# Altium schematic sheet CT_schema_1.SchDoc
size 486 x 446 mm
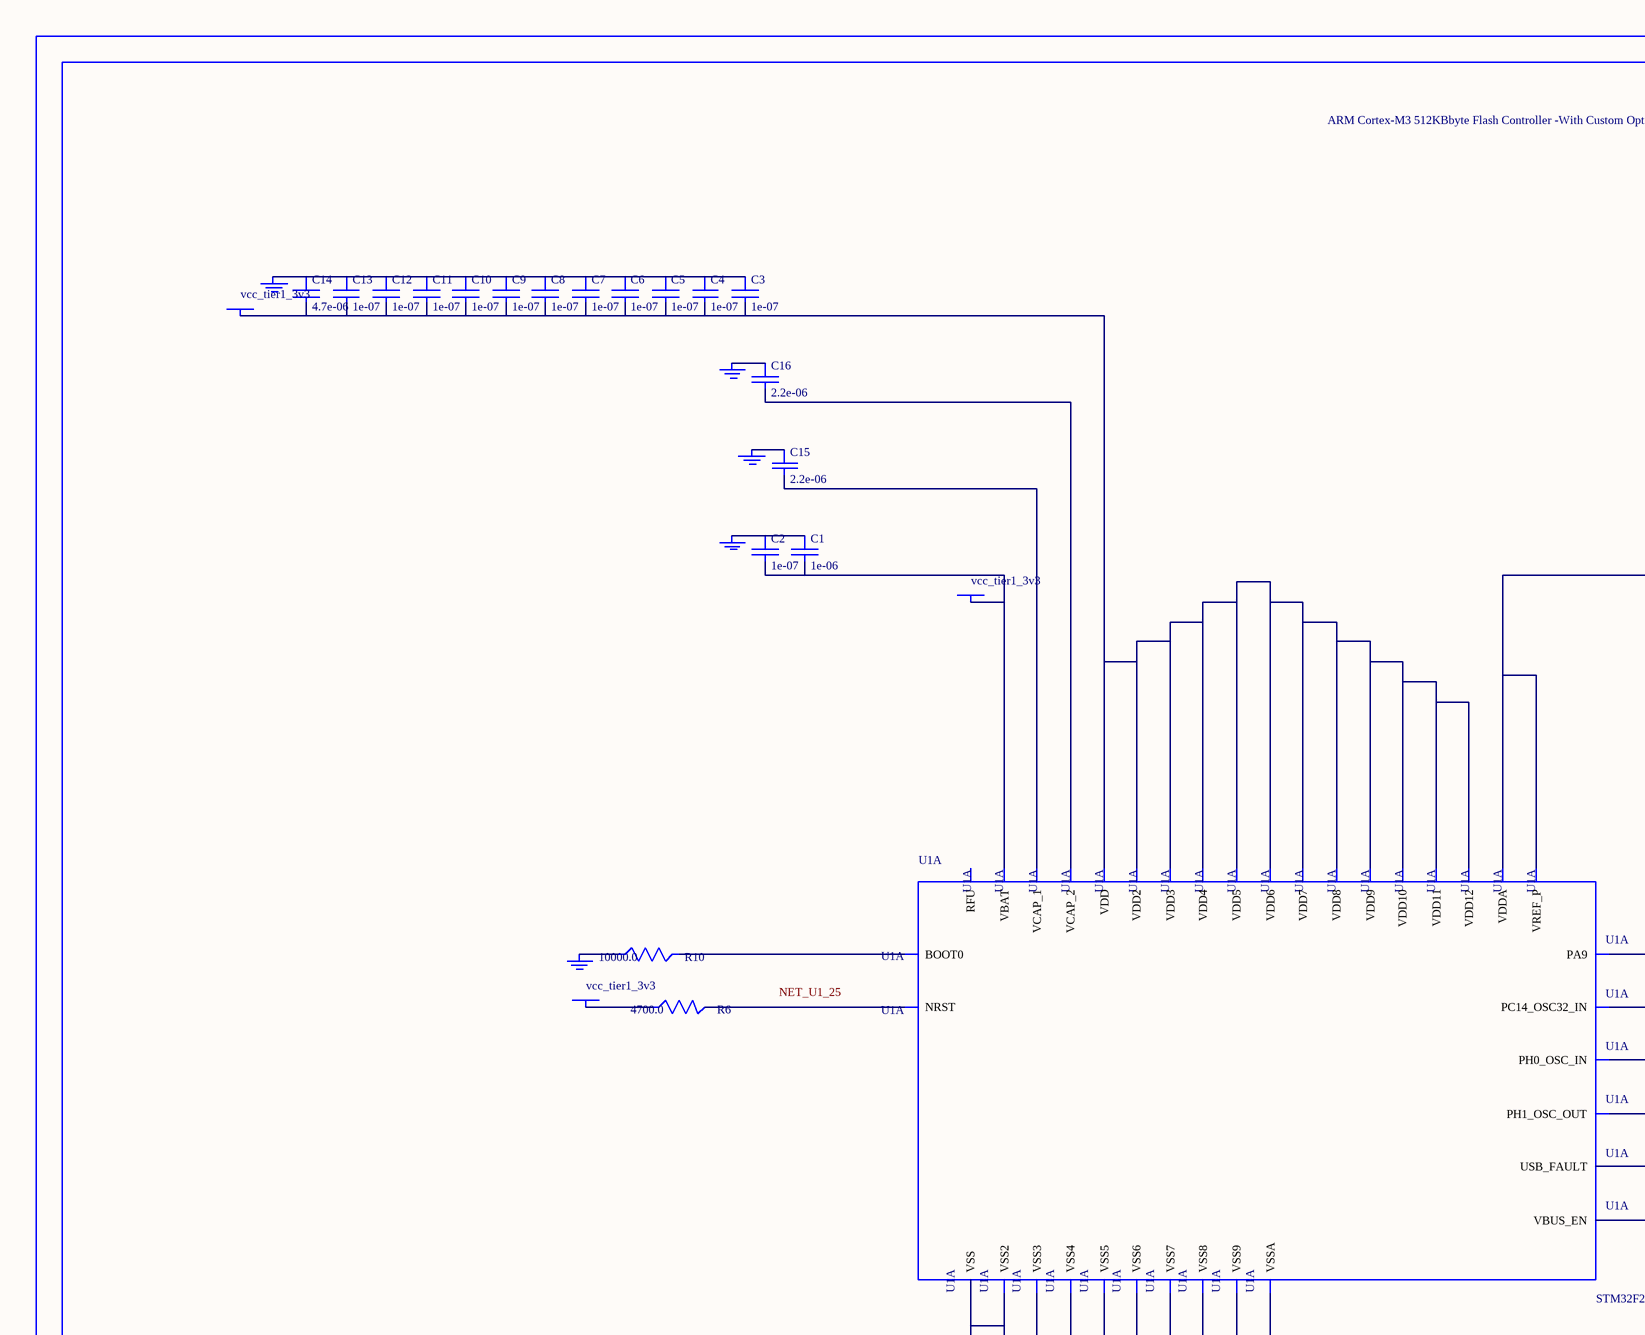
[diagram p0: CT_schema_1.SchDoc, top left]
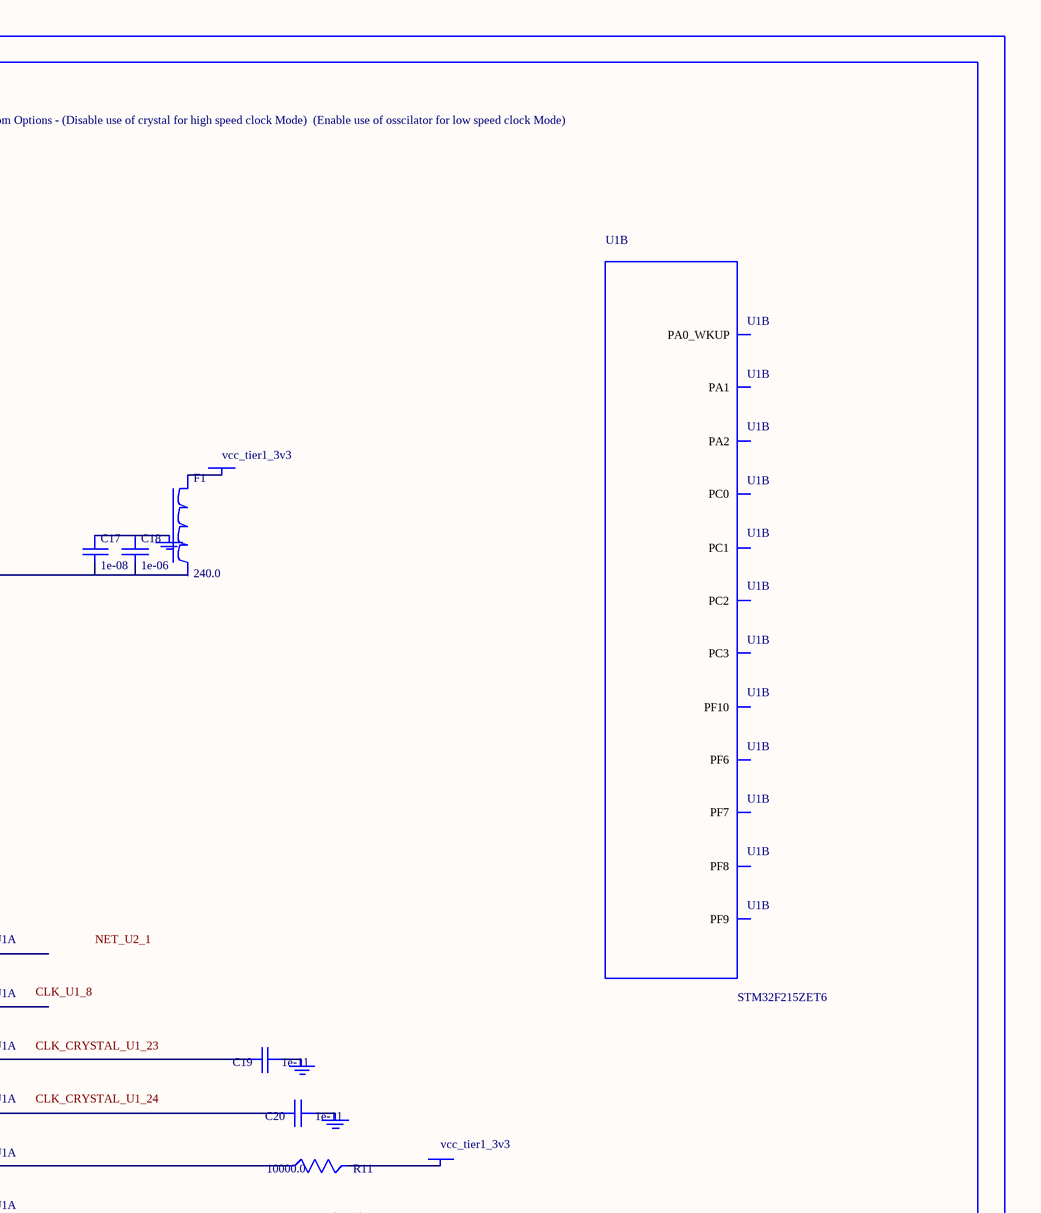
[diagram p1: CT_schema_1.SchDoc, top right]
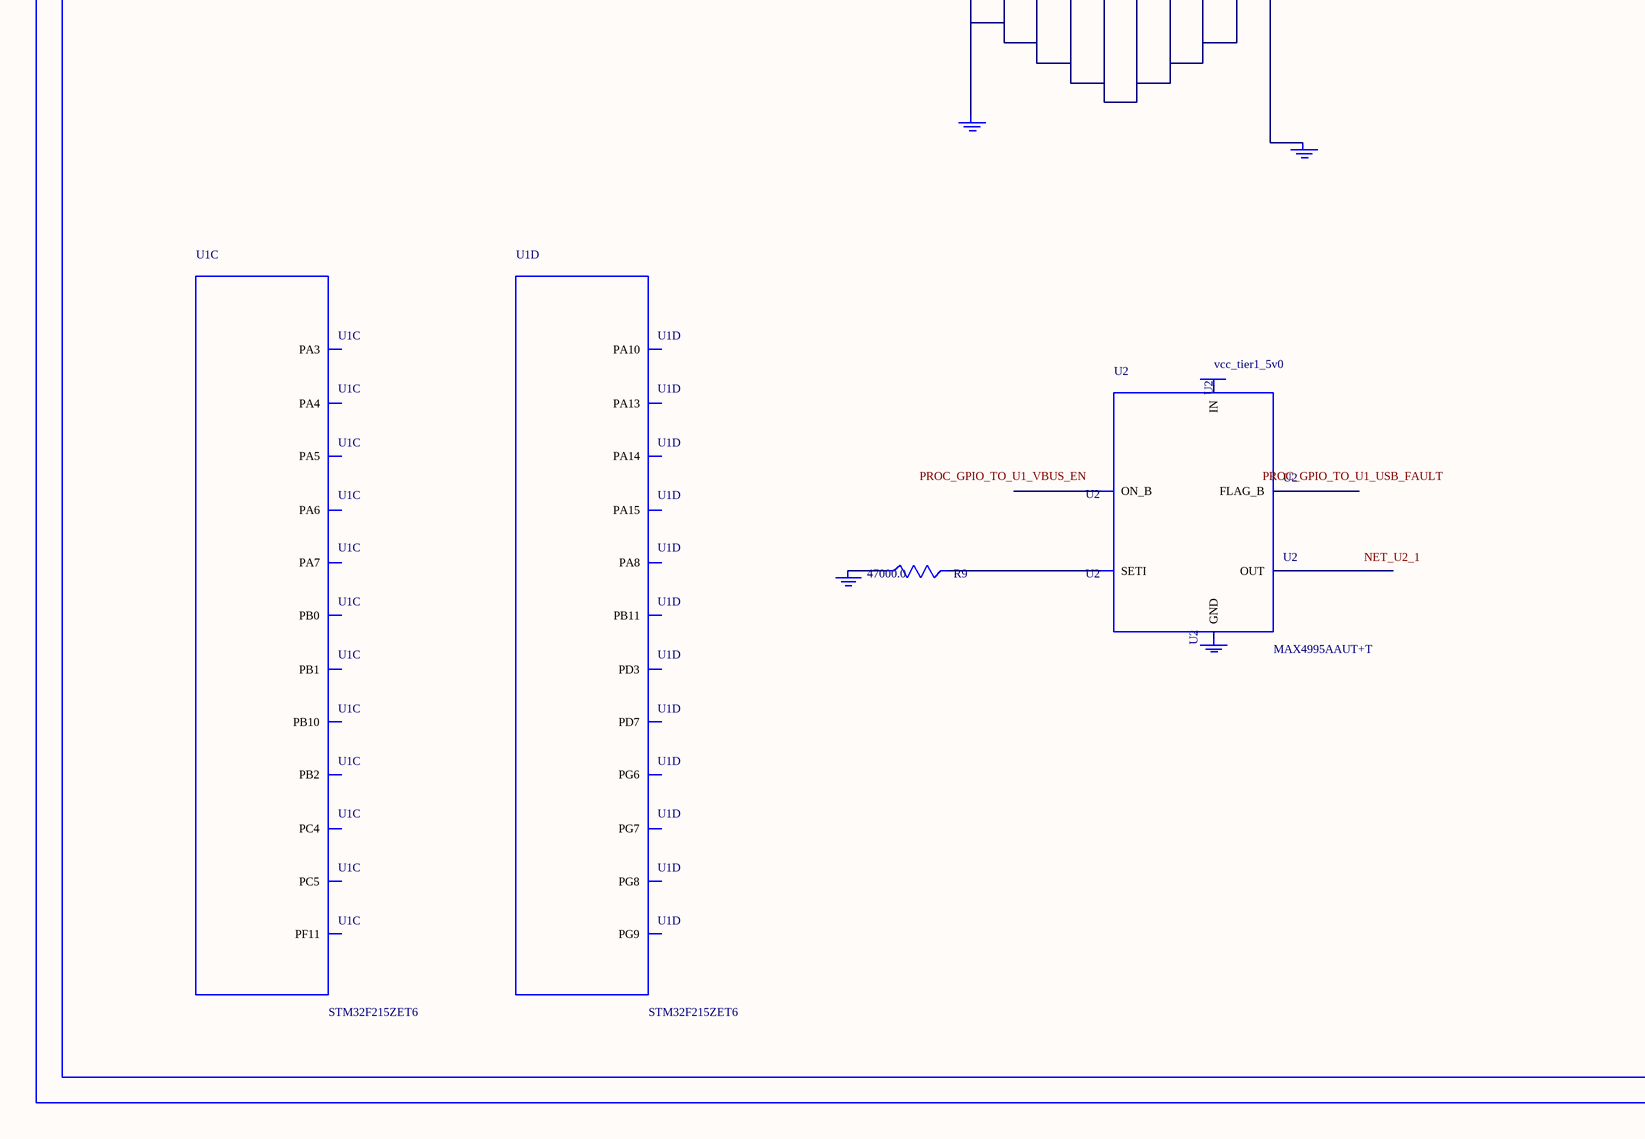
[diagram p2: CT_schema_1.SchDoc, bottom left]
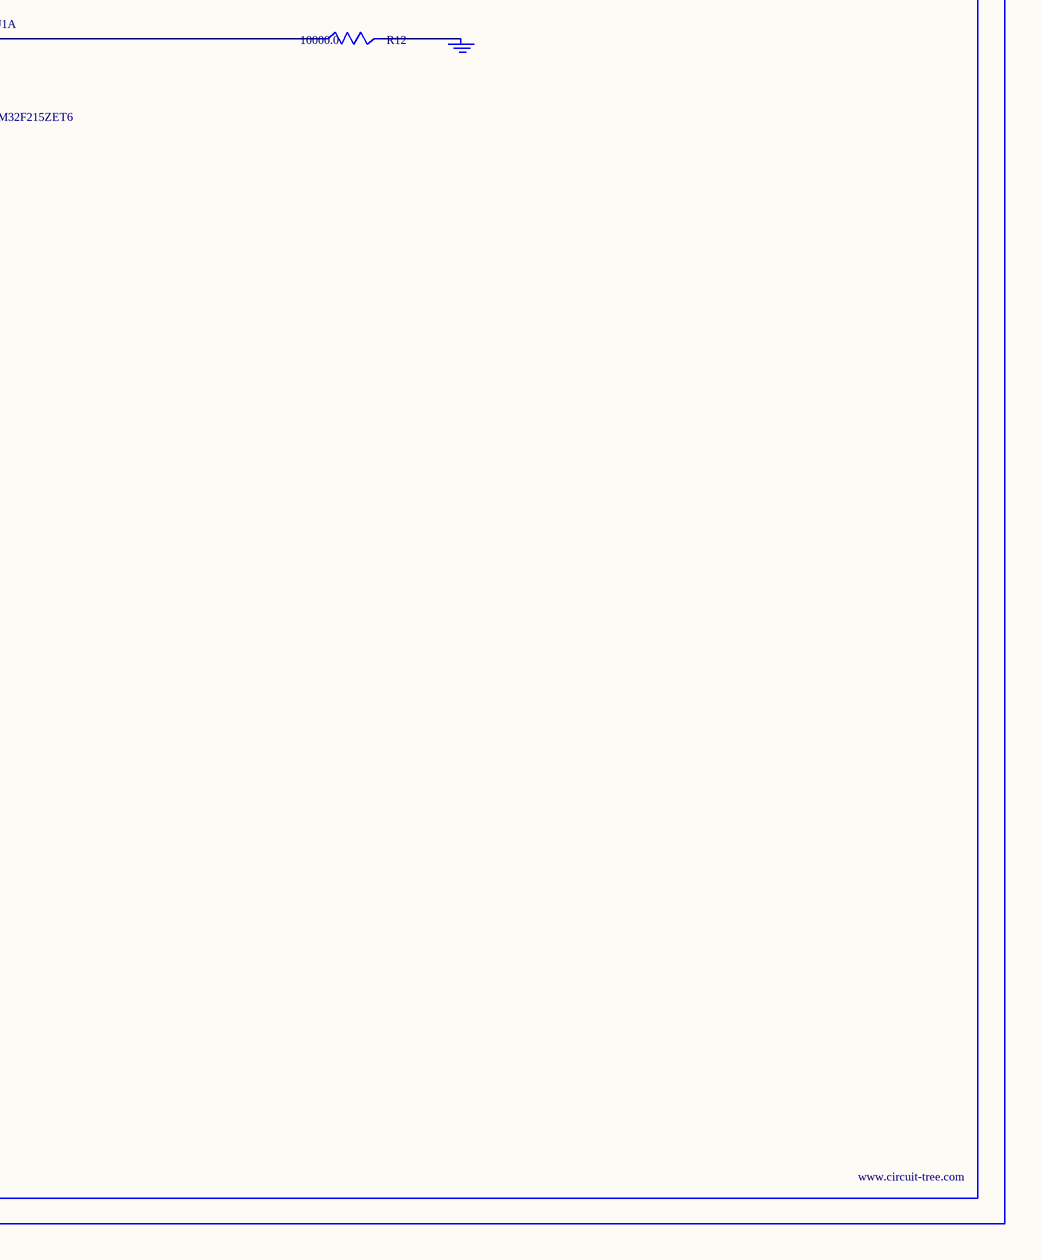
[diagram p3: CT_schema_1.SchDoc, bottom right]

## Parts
BORDER0  (no value)
C1  1e-06  [C0603]
C2  1e-07  [C0603]
C3  1e-07  [C0603]
C4  1e-07  [C0603]
C5  1e-07  [C0603]
C6  1e-07  [C0603]
C7  1e-07  [C0603]
C8  1e-07  [C0603]
C9  1e-07  [C0603]
C10  1e-07  [C0603]
C11  1e-07  [C0603]
C12  1e-07  [C0603]
C13  1e-07  [C0603]
C14  4.7e-06  [C0603]
C15  2.2e-06  [C0603]
C16  2.2e-06  [C0603]
C17  1e-08  [C0603]
C18  1e-06  [C0603]
C19  1e-11  [C0402]
C20  1e-11  [C0402]
F1  240.0  [L0603]
GND_INSTANCE_0_0  (no value)
GND_INSTANCE_0_1  (no value)
GND_INSTANCE_0_2  (no value)
GND_INSTANCE_0_3  (no value)
GND_INSTANCE_0_4  (no value)
GND_INSTANCE_0_5  (no value)
GND_INSTANCE_0_6  (no value)
GND_INSTANCE_0_7  (no value)
GND_INSTANCE_0_8  (no value)
GND_INSTANCE_0_9  (no value)
GND_INSTANCE_0_10  (no value)
GND_INSTANCE_0_11  (no value)
GND_INSTANCE_0_12  (no value)
POWER_INSTANCE_0_0  vcc_tier1_3v3
POWER_INSTANCE_0_1  vcc_tier1_3v3
POWER_INSTANCE_0_2  vcc_tier1_3v3
POWER_INSTANCE_0_3  vcc_tier1_3v3
POWER_INSTANCE_0_4  vcc_tier1_3v3
POWER_INSTANCE_0_5  vcc_tier1_5v0
R6  4700.0  [R0603]
R9  47000.0  [R0603]
R10  10000.0  [R0603]
R11  10000.0  [R0603]
R12  10000.0  [R0603]
U1  STM32F215ZET6  [LQFP144]  (parts A,B,C,D of 12)
U2  MAX4995AAUT+T  [SOT-23-6]

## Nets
NetC1_1: C1.1 C2.1 GND_INSTANCE_0_0.0(GND)
NetC1_2: C1.2 C2.2 POWER_INSTANCE_0_0.0(PWR) U1.6(VBAT)
NetC3_1: C3.1 C4.1 C5.1 C6.1 C7.1 C8.1 C9.1 C10.1 C11.1 C12.1 C13.1 C14.1 GND_INSTANCE_0_2.0(GND)
NetC3_2: C3.2 C4.2 C5.2 C6.2 C7.2 C8.2 C9.2 C10.2 C11.2 C12.2 C13.2 C14.2 POWER_INSTANCE_0_2.0(PWR) U1.17(VDD) U1.30(VDD2) U1.39(VDD3) U1.52(VDD4) U1.62(VDD5) U1.72(VDD6) U1.84(VDD7) U1.95(VDD8) U1.108(VDD9) U1.121(VDD10) U1.131(VDD11) U1.144(VDD12)
NetC15_1: C15.1 GND_INSTANCE_0_7.0(GND)
NetC15_2: C15.2 U1.71(VCAP_1)
NetC16_1: C16.1 GND_INSTANCE_0_8.0(GND)
NetC16_2: C16.2 U1.106(VCAP_2)
NetC17_1: C17.1 C18.1 GND_INSTANCE_0_6.0(GND)
NetC17_2: C17.2 C18.2 U1.32(VREF_P) U1.33(VDDA)
NetC19_1: C19.1 GND_INSTANCE_0_3.0(GND)
NetC19_2: C19.2 U1.23(PH0_OSC_IN)
NetC20_1: C20.1 GND_INSTANCE_0_4.0(GND)
NetC20_2: C20.2 U1.24(PH1_OSC_OUT)
NetF1_1: F1.1 POWER_INSTANCE_0_3.0(PWR)
NetGND_INSTANCE_0_1_0: GND_INSTANCE_0_1.0(GND) R12.2
NetGND_INSTANCE_0_5_0: GND_INSTANCE_0_5.0(GND) U1.31(VSSA)
NetGND_INSTANCE_0_9_0: GND_INSTANCE_0_9.0(GND) R10.1
NetGND_INSTANCE_0_10_0: GND_INSTANCE_0_10.0(GND) U1.16(VSS) U1.38(VSS2) U1.51(VSS3) U1.61(VSS4) U1.83(VSS5) U1.94(VSS6) U1.107(VSS7) U1.120(VSS8) U1.130(VSS9)
NetGND_INSTANCE_0_11_0: GND_INSTANCE_0_11.0(GND) R9.1
NetPOWER_INSTANCE_0_1_0: POWER_INSTANCE_0_1.0(PWR) R11.2
NetPOWER_INSTANCE_0_4_0: POWER_INSTANCE_0_4.0(PWR) R6.1
NetR6_2: R6.2 U1.25(NRST)
NetR9_2: R9.2 U2.3(SETI)
NetR10_2: R10.2 U1.138(BOOT0)
NetR11_1: R11.1 U1.9(USB_FAULT)
NetR12_1: R12.1 U1.7(VBUS_EN)

Not connected (* = marked no-connect by the designer): F1 2; GND_INSTANCE_0_12 0(GND); POWER_INSTANCE_0_5 0(PWR); U1 8(PC14_OSC32_IN) 18(PF6) 19(PF7) 20(PF8) 21(PF9) 22(PF10) 26(PC0) 27(PC1) 28(PC2) 29(PC3) 34(PA0_WKUP) 35(PA1) 36(PA2) 37(PA3) 40(PA4) 41(PA5) 42(PA6) 43(PA7) 44(PC4) 45(PC5) 46(PB0) 47(PB1) 48(PB2) 49(PF11) 69(PB10) 70(PB11) 91(PG6) 92(PG7) 93(PG8) 100(PA8) 101(PA9) 102(PA10) 105(PA13) 109(PA14) 110(PA15) 117(PD3) 123(PD7) 124(PG9) 143(RFU); U2 1(OUT) 2(GND) 4(ON_B) 5(IN) 6(FLAG_B)

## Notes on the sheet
- Labels drawn without touching a wire or pin: CLK_CRYSTAL_U1_23, CLK_CRYSTAL_U1_24, CLK_U1_8, NET_U1_25, NET_U2_1, PROC_GPIO_TO_U1_USB_FAULT, PROC_GPIO_TO_U1_VBUS_EN

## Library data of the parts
BORDER0 = BORDER_PAGE0
C1 C18 = C0603C105K3RACTU
C2-C13 = 06035C104K4Z2A
C14 = GRM188R6YA475KE15D
C15 C16 = C0603C225K8RACTU
C17 = 06035C103K4Z2A
C19 C20 = C0402C100K3GACTU
F1 = Z0603C241ASMST
GND_INSTANCE_0_0-GND_INSTANCE_0_12 = GND
POWER_INSTANCE_0_0-POWER_INSTANCE_0_5 = PWR
R6 = RC0603JR-074K7L
R9 = RC0603JR-0747KL
R10-R12 = RC0603JR-0710KL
